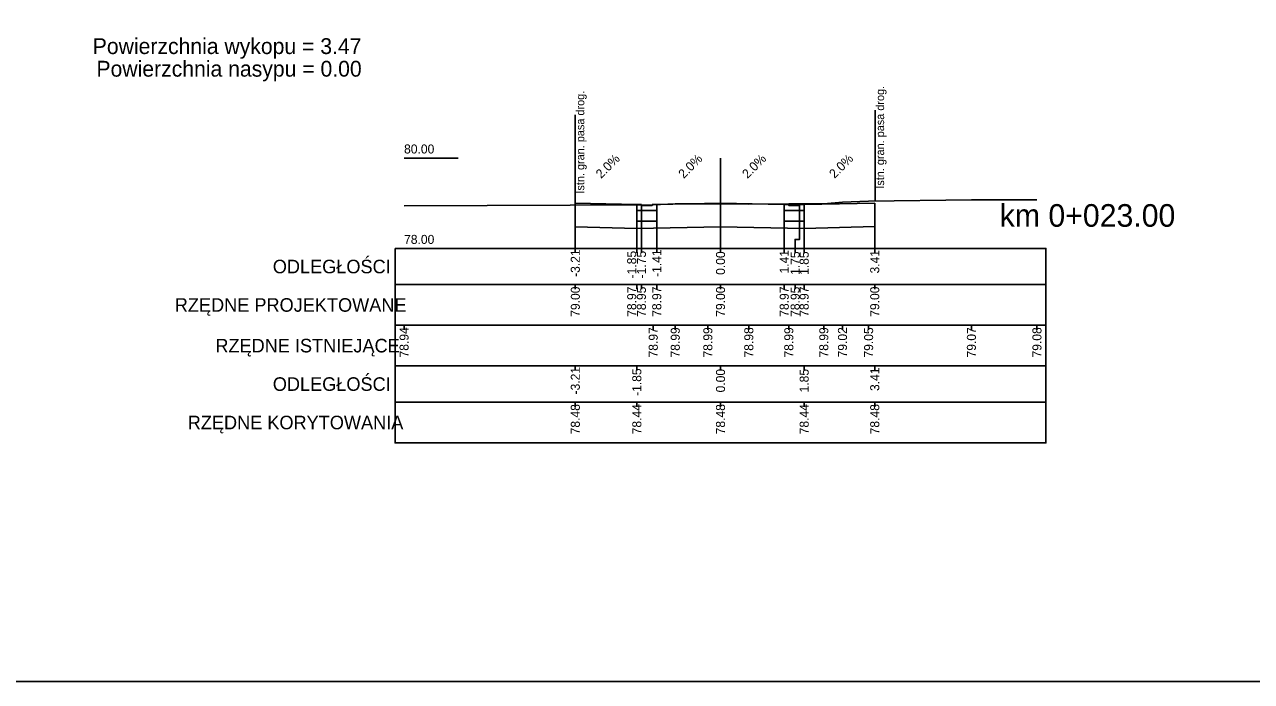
# Model space of a CAD drawing. Extents: x 7492871 to 7493499, y 5802964 to 5802992.
# Drawn here: x 7493105.36 to 7493132.5, y 5802963.88 to 5802978.41 of the extents above; entities that cross this region are included whole.
import ezdxf

# ---------------------------------------------------------------- set-up
doc = ezdxf.new("R2010")
doc.units = 0
for name, color, linetype in [('_wydruk', 7, 'Continuous'), ('d_pop_nasyp_opis', 7, 'Continuous'), ('d_pop_wykop_opis', 7, 'Continuous'), ('opisy_ramki_pop', 7, 'Continuous'), ('pop_comp_kostka', 7, 'Continuous'), ('pop_comp_lawa', 7, 'Continuous'), ('pop_comp_scieralna', 7, 'Continuous'), ('pop_granica_istn', 7, 'Continuous'), ('pop_opis', 7, 'Continuous'), ('pop_os', 7, 'Continuous'), ('pop_pikietaz', 7, 'Continuous'), ('pop_teren', 7, 'Continuous')]:
    doc.layers.add(name, color=color, linetype=linetype)

msp = doc.modelspace()

# ---------------------------------------------------------------- linework, layer by layer
msp.add_lwpolyline([(7493117.544, 5802974.457), (7493118.905, 5802974.43), (7493119.005, 5802974.43), (7493119.006, 5802974.41), (7493119.245, 5802974.41), (7493119.246, 5802974.43), (7493119.346, 5802974.43), (7493120.756, 5802974.458), (7493122.166, 5802974.43), (7493122.266, 5802974.43), (7493122.267, 5802974.41), (7493122.506, 5802974.41), (7493122.507, 5802974.43), (7493122.607, 5802974.43), (7493124.168, 5802974.461)])
at = {"layer": '_wydruk'}
msp.add_lwpolyline([(7492871.369, 5802992.281), (7493499.283, 5802992.281), (7493499.283, 5802963.881), (7492871.369, 5802963.881)], close=True, dxfattribs=at)
at = {"layer": 'opisy_ramki_pop'}
for points in [[(7493117.544, 5802973.937), (7493117.544, 5802973.659), (7493117.544, 5802973.659), (7493117.544, 5802973.459)], [(7493118.905, 5802973.901), (7493118.905, 5802973.659), (7493118.905, 5802973.659), (7493118.905, 5802973.459)], [(7493120.756, 5802973.938), (7493120.756, 5802973.659), (7493120.756, 5802973.659), (7493120.756, 5802973.459)], [(7493122.607, 5802973.901), (7493122.607, 5802973.659), (7493122.607, 5802973.659), (7493122.607, 5802973.459)], [(7493124.168, 5802973.941), (7493124.168, 5802973.659), (7493124.168, 5802973.659), (7493124.168, 5802973.459)]]:
    msp.add_lwpolyline(points, dxfattribs=at)
at = {"layer": 'pop_comp_kostka'}
for p, q in [((7493119.005, 5802974.43), (7493118.905, 5802974.43)), ((7493118.905, 5802974.43), (7493118.905, 5802974.3)), ((7493119.006, 5802974.41), (7493119.005, 5802974.43)), ((7493119.246, 5802974.43), (7493119.245, 5802974.41)), ((7493119.346, 5802974.43), (7493119.246, 5802974.43)), ((7493119.346, 5802974.3), (7493119.346, 5802974.43)), ((7493122.266, 5802974.43), (7493122.166, 5802974.43)), ((7493122.166, 5802974.43), (7493122.166, 5802974.3)), ((7493122.267, 5802974.41), (7493122.266, 5802974.43)), ((7493122.507, 5802974.43), (7493122.506, 5802974.41)), ((7493122.607, 5802974.43), (7493122.507, 5802974.43)), ((7493122.607, 5802974.3), (7493122.607, 5802974.43)), ((7493118.905, 5802974.3), (7493119.346, 5802974.3)), ((7493119.245, 5802974.41), (7493119.006, 5802974.41)), ((7493122.166, 5802974.3), (7493122.607, 5802974.3)), ((7493122.506, 5802974.41), (7493122.267, 5802974.41))]:
    msp.add_line(p, q, dxfattribs=at)
at = {"layer": 'pop_comp_lawa'}
for p, q in [((7493119.346, 5802974.3), (7493118.905, 5802974.3)), ((7493118.905, 5802974.3), (7493118.905, 5802974.06)), ((7493119.346, 5802974.06), (7493119.346, 5802974.3)), ((7493122.607, 5802974.3), (7493122.166, 5802974.3)), ((7493122.166, 5802974.3), (7493122.166, 5802974.06)), ((7493122.607, 5802974.06), (7493122.607, 5802974.3)), ((7493118.905, 5802974.06), (7493119.346, 5802974.06)), ((7493122.166, 5802974.06), (7493122.607, 5802974.06))]:
    msp.add_line(p, q, dxfattribs=at)
at = {"layer": 'pop_comp_scieralna'}
for p, q in [((7493118.905, 5802974.43), (7493117.544, 5802974.457)), ((7493117.544, 5802974.457), (7493117.544, 5802973.937)), ((7493118.905, 5802974.06), (7493118.905, 5802974.43)), ((7493120.756, 5802974.458), (7493119.346, 5802974.43)), ((7493119.346, 5802974.43), (7493119.346, 5802974.06)), ((7493120.756, 5802973.938), (7493120.756, 5802974.458)), ((7493122.166, 5802974.43), (7493120.756, 5802974.458)), ((7493120.756, 5802974.458), (7493120.756, 5802973.938)), ((7493122.166, 5802974.06), (7493122.166, 5802974.43)), ((7493124.168, 5802974.461), (7493122.607, 5802974.43)), ((7493122.607, 5802974.43), (7493122.607, 5802974.06)), ((7493124.168, 5802973.941), (7493124.168, 5802974.461)), ((7493117.544, 5802973.937), (7493118.905, 5802973.901)), ((7493119.346, 5802974.06), (7493118.905, 5802974.06)), ((7493118.905, 5802973.901), (7493120.756, 5802973.938)), ((7493120.756, 5802973.938), (7493122.607, 5802973.901)), ((7493122.607, 5802974.06), (7493122.166, 5802974.06)), ((7493122.607, 5802973.901), (7493124.168, 5802973.941))]:
    msp.add_line(p, q, dxfattribs=at)
at = {"layer": 'pop_granica_istn'}
for p, q in [((7493117.544, 5802974.911), (7493117.544, 5802976.411)), ((7493124.177, 5802975.019), (7493124.177, 5802976.519)), ((7493124.177, 5802974.519), (7493124.177, 5802975.019)), ((7493117.544, 5802974.411), (7493117.544, 5802974.911))]:
    msp.add_line(p, q, dxfattribs=at)
at = {"layer": 'pop_opis'}
for p, q in [((7493113.756, 5802975.459), (7493114.956, 5802975.459)), ((7493113.556, 5802973.459), (7493113.556, 5802971.759)), ((7493113.556, 5802973.459), (7493113.556, 5802971.759)), ((7493113.556, 5802973.459), (7493113.556, 5802971.759)), ((7493113.556, 5802973.459), (7493113.556, 5802971.759)), ((7493113.756, 5802973.459), (7493114.956, 5802973.459)), ((7493117.544, 5802973.359), (7493117.544, 5802973.459)), ((7493118.905, 5802973.359), (7493118.905, 5802973.459)), ((7493119.006, 5802973.359), (7493119.006, 5802973.459)), ((7493119.346, 5802973.359), (7493119.346, 5802973.459)), ((7493120.756, 5802973.359), (7493120.756, 5802973.459)), ((7493122.166, 5802973.359), (7493122.166, 5802973.459)), ((7493122.407, 5802973.359), (7493122.407, 5802973.459)), ((7493122.607, 5802973.359), (7493122.607, 5802973.459)), ((7493124.168, 5802973.359), (7493124.168, 5802973.459)), ((7493113.556, 5802972.659), (7493127.956, 5802972.659)), ((7493113.556, 5802972.659), (7493127.956, 5802972.659)), ((7493113.556, 5802972.659), (7493127.956, 5802972.659)), ((7493113.556, 5802972.659), (7493127.956, 5802972.659)), ((7493117.544, 5802972.559), (7493117.544, 5802972.659)), ((7493118.905, 5802972.559), (7493118.905, 5802972.659)), ((7493119.006, 5802972.559), (7493119.006, 5802972.659)), ((7493119.346, 5802972.559), (7493119.346, 5802972.659)), ((7493120.756, 5802972.559), (7493120.756, 5802972.659)), ((7493122.166, 5802972.559), (7493122.166, 5802972.659)), ((7493122.407, 5802972.559), (7493122.407, 5802972.659)), ((7493122.607, 5802972.559), (7493122.607, 5802972.659)), ((7493124.168, 5802972.559), (7493124.168, 5802972.659)), ((7493113.556, 5802971.759), (7493113.556, 5802970.859)), ((7493113.756, 5802971.659), (7493113.756, 5802971.759)), ((7493119.268, 5802971.659), (7493119.268, 5802971.759)), ((7493119.755, 5802971.659), (7493119.755, 5802971.759)), ((7493120.476, 5802971.659), (7493120.476, 5802971.759)), ((7493121.382, 5802971.659), (7493121.382, 5802971.759)), ((7493122.267, 5802971.659), (7493122.267, 5802971.759)), ((7493123.041, 5802971.659), (7493123.041, 5802971.759)), ((7493123.454, 5802971.659), (7493123.454, 5802971.759)), ((7493124.032, 5802971.659), (7493124.032, 5802971.759)), ((7493126.306, 5802971.659), (7493126.306, 5802971.759)), ((7493127.756, 5802971.659), (7493127.756, 5802971.759)), ((7493113.556, 5802970.859), (7493113.556, 5802969.159)), ((7493117.544, 5802970.759), (7493117.544, 5802970.859)), ((7493118.905, 5802970.759), (7493118.905, 5802970.859)), ((7493120.756, 5802970.759), (7493120.756, 5802970.859)), ((7493122.607, 5802970.759), (7493122.607, 5802970.859)), ((7493124.168, 5802970.759), (7493124.168, 5802970.859)), ((7493113.556, 5802970.059), (7493127.956, 5802970.059)), ((7493117.544, 5802969.959), (7493117.544, 5802970.059)), ((7493118.905, 5802969.959), (7493118.905, 5802970.059)), ((7493120.756, 5802969.959), (7493120.756, 5802970.059)), ((7493122.607, 5802969.959), (7493122.607, 5802970.059)), ((7493124.168, 5802969.959), (7493124.168, 5802970.059))]:
    msp.add_line(p, q, dxfattribs=at)
for points in [[(7493117.544, 5802974.457), (7493117.544, 5802973.659), (7493117.544, 5802973.659), (7493117.544, 5802973.459)], [(7493118.905, 5802974.43), (7493118.905, 5802973.659), (7493118.905, 5802973.659), (7493118.905, 5802973.459)], [(7493119.346, 5802974.43), (7493119.346, 5802973.659), (7493119.346, 5802973.659), (7493119.346, 5802973.459)], [(7493120.756, 5802974.458), (7493120.756, 5802973.659), (7493120.756, 5802973.659), (7493120.756, 5802973.459)], [(7493122.166, 5802974.43), (7493122.166, 5802973.659), (7493122.166, 5802973.659), (7493122.166, 5802973.459)], [(7493122.607, 5802974.43), (7493122.607, 5802973.659), (7493122.607, 5802973.659), (7493122.607, 5802973.459)], [(7493124.168, 5802974.461), (7493124.168, 5802973.659), (7493124.168, 5802973.659), (7493124.168, 5802973.459)], [(7493119.006, 5802974.41), (7493119.006, 5802973.659), (7493119.006, 5802973.659), (7493119.006, 5802973.459)], [(7493122.506, 5802974.41), (7493122.506, 5802973.659), (7493122.407, 5802973.659), (7493122.407, 5802973.459)]]:
    msp.add_lwpolyline(points, dxfattribs=at)
for points in [[(7493113.556, 5802973.459), (7493113.556, 5802971.759), (7493127.956, 5802971.759), (7493127.956, 5802973.459)], [(7493113.556, 5802973.459), (7493113.556, 5802971.759), (7493127.956, 5802971.759), (7493127.956, 5802973.459)], [(7493113.556, 5802973.459), (7493113.556, 5802971.759), (7493127.956, 5802971.759), (7493127.956, 5802973.459)], [(7493113.556, 5802973.459), (7493113.556, 5802971.759), (7493127.956, 5802971.759), (7493127.956, 5802973.459)], [(7493113.556, 5802971.759), (7493113.556, 5802970.859), (7493127.956, 5802970.859), (7493127.956, 5802971.759)], [(7493113.556, 5802970.859), (7493113.556, 5802969.159), (7493127.956, 5802969.159), (7493127.956, 5802970.859)]]:
    msp.add_lwpolyline(points, close=True, dxfattribs=at)
at = {"layer": 'pop_os'}
msp.add_line((7493120.756, 5802975.459), (7493120.756, 5802973.459), dxfattribs=at)
at = {"layer": 'pop_teren'}
msp.add_lwpolyline([(7493113.756, 5802974.402), (7493119.268, 5802974.427), (7493119.755, 5802974.446), (7493120.476, 5802974.447), (7493121.382, 5802974.435), (7493122.267, 5802974.447), (7493123.041, 5802974.448), (7493123.454, 5802974.479), (7493124.032, 5802974.504), (7493126.306, 5802974.531), (7493127.756, 5802974.536)], dxfattribs=at)

# ---------------------------------------------------------------- texts
at = {"layer": 'd_pop_nasyp_opis'}
msp.add_text('Powierzchnia nasypu = 0.00', height=0.35, dxfattribs=at).set_placement((7493106.951, 5802977.259))
at = {"layer": 'd_pop_wykop_opis'}
msp.add_text('Powierzchnia wykopu = 3.47', height=0.35, dxfattribs=at).set_placement((7493106.869, 5802977.759))
at = {"layer": 'pop_granica_istn'}
for p in [(7493117.742, 5802974.672), (7493124.375, 5802974.78)]:
    msp.add_text('Istn. gran. pasa drog.', height=0.18, rotation=90, dxfattribs=at).set_placement(p)
at = {"layer": 'pop_opis'}
for s, height, p in [('80.00', 0.2, (7493113.756, 5802975.559)), ('78.00', 0.2, (7493113.756, 5802973.559)), ('ODLEGŁOŚCI', 0.3, (7493110.852, 5802972.909)), ('ODLEGŁOŚCI', 0.3, (7493110.852, 5802972.909)), ('ODLEGŁOŚCI', 0.3, (7493110.852, 5802972.909)), ('ODLEGŁOŚCI', 0.3, (7493110.852, 5802972.909)), ('RZĘDNE PROJEKTOWANE', 0.3, (7493108.684, 5802972.059)), ('RZĘDNE PROJEKTOWANE', 0.3, (7493108.684, 5802972.059)), ('RZĘDNE PROJEKTOWANE', 0.3, (7493108.684, 5802972.059)), ('RZĘDNE PROJEKTOWANE', 0.3, (7493108.684, 5802972.059)), ('RZĘDNE ISTNIEJĄCE', 0.3, (7493109.581, 5802971.159)), ('ODLEGŁOŚCI', 0.3, (7493110.852, 5802970.309)), ('RZĘDNE KORYTOWANIA', 0.3, (7493108.97, 5802969.459))]:
    msp.add_text(s, height=height, dxfattribs=at).set_placement(p)
for s, rotation, p in [('2.0%', 45, (7493118.116, 5802974.994)), ('2.0%', 45, (7493119.943, 5802974.994)), ('2.0%', 45, (7493121.353, 5802974.994)), ('2.0%', 45, (7493123.279, 5802974.996)), ('-3.21', 90, (7493117.644, 5802972.829)), ('-1.85', 90, (7493118.892, 5802972.796)), ('-1.75', 90, (7493119.106, 5802972.796)), ('-1.41', 90, (7493119.446, 5802972.829)), ('0.00', 90, (7493120.856, 5802972.874)), ('1.41', 90, (7493122.266, 5802972.905)), ('1.75', 90, (7493122.507, 5802972.873)), ('1.85', 90, (7493122.707, 5802972.873)), ('3.41', 90, (7493124.268, 5802972.905)), ('79.00', 90, (7493117.644, 5802971.947)), ('78.97', 90, (7493118.892, 5802971.947)), ('78.95', 90, (7493119.106, 5802971.945)), ('78.97', 90, (7493119.446, 5802971.947)), ('79.00', 90, (7493120.856, 5802971.947)), ('78.97', 90, (7493122.266, 5802971.947)), ('78.95', 90, (7493122.507, 5802971.945)), ('78.97', 90, (7493122.707, 5802971.947)), ('79.00', 90, (7493124.268, 5802971.947)), ('78.94', 90, (7493113.856, 5802971.047)), ('78.97', 90, (7493119.368, 5802971.047)), ('78.99', 90, (7493119.855, 5802971.046)), ('78.99', 90, (7493120.576, 5802971.046)), ('78.98', 90, (7493121.482, 5802971.046)), ('78.99', 90, (7493122.367, 5802971.046)), ('78.99', 90, (7493123.141, 5802971.046)), ('79.02', 90, (7493123.554, 5802971.048)), ('79.05', 90, (7493124.132, 5802971.045)), ('79.07', 90, (7493126.406, 5802971.047)), ('79.08', 90, (7493127.856, 5802971.046)), ('-3.21', 90, (7493117.644, 5802970.229)), ('-1.85', 90, (7493119.005, 5802970.196)), ('0.00', 90, (7493120.856, 5802970.274)), ('1.85', 90, (7493122.707, 5802970.273)), ('3.41', 90, (7493124.268, 5802970.305)), ('78.48', 90, (7493117.644, 5802969.346)), ('78.44', 90, (7493119.005, 5802969.347)), ('78.48', 90, (7493120.856, 5802969.346)), ('78.44', 90, (7493122.707, 5802969.347)), ('78.48', 90, (7493124.268, 5802969.346))]:
    msp.add_text(s, height=0.2, rotation=rotation, dxfattribs=at).set_placement(p)
at = {"layer": 'pop_pikietaz'}
msp.add_text('km 0+023.00', height=0.5, dxfattribs=at).set_placement((7493126.933, 5802973.939))

doc.saveas('drawing.dxf')
